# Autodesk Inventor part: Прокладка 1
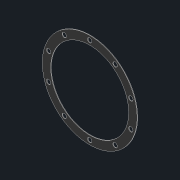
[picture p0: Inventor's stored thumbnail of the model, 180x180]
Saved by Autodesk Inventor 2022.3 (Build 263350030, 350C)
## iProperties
Created: 2022-08
Part Number: Прокладка 1
Material: Резина
Document SubType Name: Modeling
Designer: Карташов
Density: 0.93 g/cm^3
Appearance: Резина — черная
Author: Карташов
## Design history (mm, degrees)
sketch "Эскиз1"
  geometry: L1 (-320, -7.5)-(-320, 7.5) reference; L2 (-320, -7.5)-(-208, -7.5) reference; L3 (-68, -7.5)-(-25, -7.5) reference; L4 (105, -7.5)-(145, -7.5) reference; L5 (235, -7.5)-(320, -7.5) reference; L6 (320, 7.5)-(320, -7.5) reference; L7 (320, 7.5)-(248.095, 7.5) reference; L8 (195, 52.291)-(195, 82.5) reference; L9 (185, 82.5)-(195, 82.5) reference; L10 (185, 82.5)-(185, 52.291) reference; L11 (131.905, 7.5)-(118.581, 7.5) reference; L12 (70, 66.662)-(70, 77.5) reference; L13 (60, 77.5)-(70, 77.5) reference; L14 (60, 77.5)-(60, 69.96) reference; L15 (20, 69.96)-(20, 77.5) reference; L16 (10, 77.5)-(20, 77.5) reference; L17 (10, 77.5)-(10, 66.662) reference; L18 (-38.581, 7.5)-(-54.334, 7.5) reference; L19 (-108, 72.03)-(-108, 82.5) reference; L20 (-118, 82.5)-(-108, 82.5) reference; L21 (-118, 82.5)-(-118, 75.114) reference; L22 (-158, 75.114)-(-158, 82.5) reference; L23 (-168, 82.5)-(-158, 82.5) reference; L24 (-168, 82.5)-(-168, 72.03) reference; L25 (-221.666, 7.5)-(-320, 7.5) reference; L26 (-208, -7.5)-(-320, -7.5) reference; L27 (-320, -7.5)-(-320, -22.5) reference; L28 (-320, -22.5)-(-305, -22.5) reference; L29 (-300, -27.5)-(-300, -187.5) reference; L30 (-300, -187.5)-(-285, -187.5) reference; L31 (-285, -27.5)-(-285, -187.5) reference; L32 (-221.666, -22.5)-(-280, -22.5) reference; L33 (-38.581, -22.5)-(-54.334, -22.5) reference; L34 (131.905, -22.5)-(118.581, -22.5) reference; L35 (280, -22.5)-(248.095, -22.5) reference; L36 (285, -187.5)-(285, -27.5) reference; L37 (285, -187.5)-(300, -187.5) reference; L38 (300, -187.5)-(300, -27.5) reference; L39 (320, -22.5)-(305, -22.5) reference; L40 (320, -22.5)-(320, -7.5) reference; L41 (320, -7.5)-(235, -7.5) reference; L42 (145, -7.5)-(105, -7.5) reference; L43 (-25, -7.5)-(-68, -7.5) reference; C1 r 4 at (-138, 70) reference; C2 r 4 at (-2.614, 51.154) reference; C3 r 4 at (144.534, 18.75) reference; C4 r 4 at (190, 45) reference; C5 r 4 at (40, 65) reference; C6 r 4 at (-92.447, 55.199) reference; C7 r 4 at (-183.553, 55.199) reference; C8 r 4 at (-28.952, 14.904) reference; C9 r 4 at (108.952, 14.904) reference; C10 r 4 at (235.466, 18.75) reference; C11 r 4 at (82.614, 51.154) reference; C12 r 4 at (-64.293, 16.449) reference; C13 r 4 at (-211.707, 16.449) reference; C14 r 4 at (144.534, -33.75) reference; C15 r 4 at (235.466, -33.75) reference; C16 r 4 at (190, -60) reference; C17 r 4 at (82.614, -66.154) reference; C18 r 4 at (108.952, -29.904) reference; C19 r 4 at (-28.952, -29.904) reference; C20 r 4 at (-2.614, -66.154) reference; C21 r 4 at (40, -80) reference; C22 r 4 at (-92.447, -70.199) reference; C23 r 4 at (-64.293, -31.449) reference; C24 r 4 at (-211.707, -31.449) reference; C25 r 4 at (-183.553, -70.199) reference; C26 r 4 at (-138, -85) reference; C27 r 85 at (-138, -7.5); A1 r 70 centre (-138, -7.5) between (-68, -7.5) and (-208, -7.5) reference; A2 r 65 centre (40, -7.5) between (105, -7.5) and (-25, -7.5) reference; A3 r 45 centre (190, -7.5) between (235, -7.5) and (145, -7.5) reference; A4 r 60 centre (190, -7.5) between (248.095, 7.5) and (195, 52.291) reference; A5 r 60 centre (190, -7.5) between (185, 52.291) and (131.905, 7.5) reference; A6 r 80 centre (40, -7.5) between (118.581, 7.5) and (70, 66.662) reference; A7 r 80 centre (40, -7.5) between (60, 69.96) and (20, 69.96) reference; A8 r 80 centre (40, -7.5) between (10, 66.662) and (-38.581, 7.5) reference; A9 r 85 centre (-138, -7.5) between (-54.334, 7.5) and (-108, 72.03) reference; A10 r 85 centre (-138, -7.5) between (-118, 75.114) and (-158, 75.114) reference; A11 r 85 centre (-138, -7.5) between (-168, 72.03) and (-221.666, 7.5) reference; A12 r 5 centre (-305, -27.5) between (-300, -27.5) and (-305, -22.5) reference; A13 r 5 centre (-280, -27.5) between (-280, -22.5) and (-285, -27.5) reference; A14 r 85 centre (-138, -7.5) between (-221.666, -22.5) and (-168, -87.03) reference; A15 r 85 centre (-138, -7.5) between (-168, -87.03) and (-158, -90.114) reference; A16 r 85 centre (-138, -7.5) between (-158, -90.114) and (-118, -90.114) reference; A17 r 85 centre (-138, -7.5) between (-118, -90.114) and (-108, -87.03) reference; A18 r 85 centre (-138, -7.5) between (-108, -87.03) and (-54.334, -22.5) reference; A19 r 80 centre (40, -7.5) between (-38.581, -22.5) and (10, -81.662) reference; A20 r 80 centre (40, -7.5) between (10, -81.662) and (20, -84.96) reference; A21 r 80 centre (40, -7.5) between (20, -84.96) and (60, -84.96) reference; A22 r 80 centre (40, -7.5) between (60, -84.96) and (70, -81.662) reference; A23 r 80 centre (40, -7.5) between (70, -81.662) and (118.581, -22.5) reference; A24 r 60 centre (190, -7.5) between (131.905, -22.5) and (160, -59.462) reference; A25 r 60 centre (190, -7.5) between (160, -59.462) and (170, -64.069) reference; A26 r 60 centre (190, -7.5) between (170, -64.069) and (210, -64.069) reference; A27 r 60 centre (190, -7.5) between (210, -64.069) and (220, -59.462) reference; A28 r 60 centre (190, -7.5) between (220, -59.462) and (248.095, -22.5) reference; A29 r 5 centre (280, -27.5) between (285, -27.5) and (280, -22.5) reference; A30 r 5 centre (305, -27.5) between (305, -22.5) and (300, -27.5) reference; A31 r 45 centre (190, -7.5) between (145, -7.5) and (235, -7.5) reference; A32 r 65 centre (40, -7.5) between (-25, -7.5) and (105, -7.5) reference; A33 r 70 centre (-138, -7.5) between (-208, -7.5) and (-68, -7.5) reference; 9 further points
  constraints: 1 centre point, 1 coincident, 1 concentric
extrude "Выдавливание1" new body sketch "Эскиз1" distance "d0" = 1; taper "d1" = 0 deg
node "Твердое тело1"
node "Ссылка1"
node "Ссылка2"
